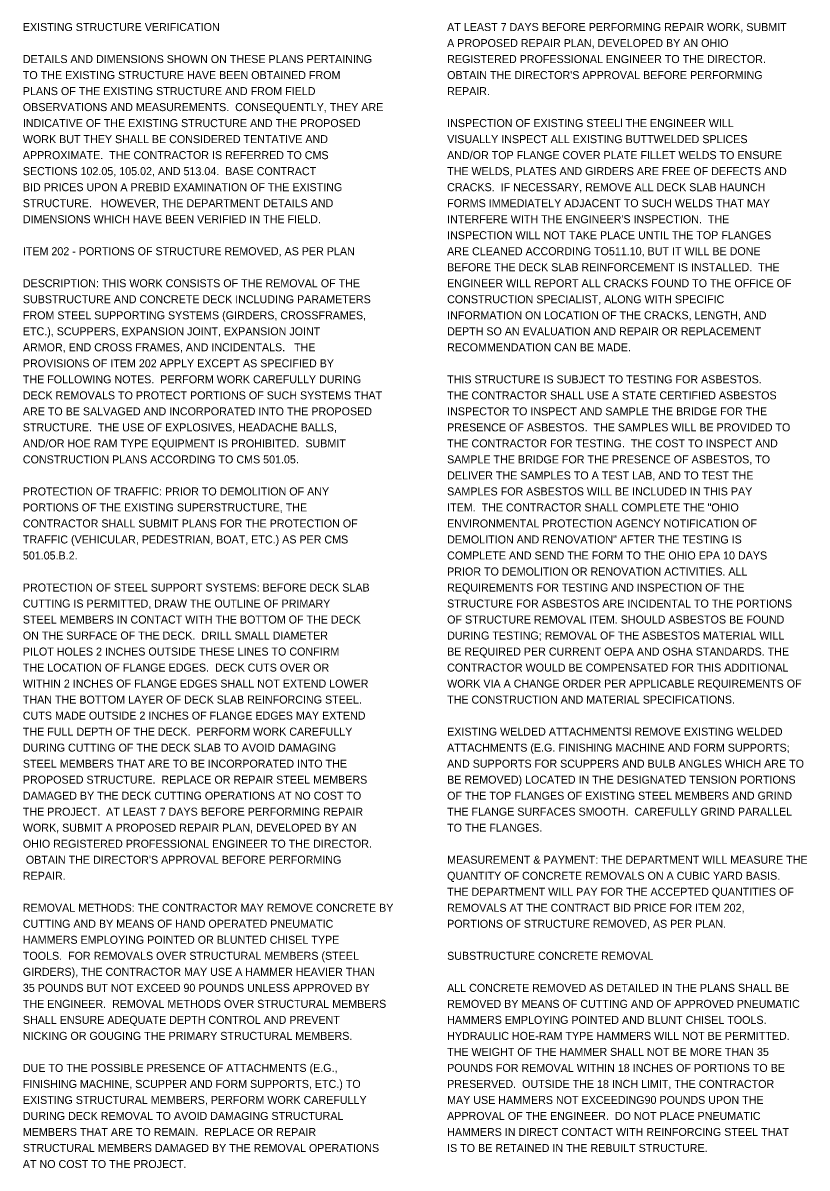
# Model space of a CAD drawing. Extents: x -51.6 to 45.5, y -38.3 to 35.3.
# Drawn here: x -44.16 to -30.45, y 15.28 to 35.3 of the extents above; entities that cross this region are included whole.
import ezdxf

# ---------------------------------------------------------------- set-up
doc = ezdxf.new("R2010")
doc.units = 0
doc.layers.add('BD_P_Text', color=7, linetype='Continuous')

msp = doc.modelspace()

# ---------------------------------------------------------------- texts
at = {"layer": 'BD_P_Text'}
for s, p in [('EXISTING STRUCTURE VERIFICATION', (-44.163, 35.157)), ('AT LEAST 7 DAYS BEFORE PERFORMING REPAIR WORK, SUBMIT ', (-36.743, 35.157)), ('A PROPOSED REPAIR PLAN, DEVELOPED BY AN OHIO ', (-36.743, 34.877)), ('DETAILS AND DIMENSIONS SHOWN ON THESE PLANS PERTAINING ', (-44.163, 34.597)), ('REGISTERED PROFESSIONAL ENGINEER TO THE DIRECTOR.  ', (-36.743, 34.597)), ('TO THE EXISTING STRUCTURE HAVE BEEN OBTAINED FROM ', (-44.163, 34.317)), ("OBTAIN THE DIRECTOR'S APPROVAL BEFORE PERFORMING ", (-36.743, 34.317)), ('PLANS OF THE EXISTING STRUCTURE AND FROM FIELD ', (-44.163, 34.037)), ('REPAIR.', (-36.743, 34.037)), ('OBSERVATIONS AND MEASUREMENTS.  CONSEQUENTLY, THEY ARE ', (-44.163, 33.757)), ('INDICATIVE OF THE EXISTING STRUCTURE AND THE PROPOSED ', (-44.163, 33.477)), ('INSPECTION OF EXISTING STEELl THE ENGINEER WILL ', (-36.743, 33.477)), ('WORK BUT THEY SHALL BE CONSIDERED TENTATIVE AND ', (-44.163, 33.197)), ('VISUALLY INSPECT ALL EXISTING BUTTWELDED SPLICES ', (-36.743, 33.197)), ('APPROXIMATE.  THE CONTRACTOR IS REFERRED TO CMS ', (-44.163, 32.917)), ('AND/OR TOP FLANGE COVER PLATE FILLET WELDS TO ENSURE ', (-36.743, 32.917)), ('SECTIONS 102.05, 105.02, AND 513.04.  BASE CONTRACT ', (-44.163, 32.637)), ('THE WELDS, PLATES AND GIRDERS ARE FREE OF DEFECTS AND ', (-36.743, 32.637)), ('BID PRICES UPON A PREBID EXAMINATION OF THE EXISTING ', (-44.163, 32.357)), ('CRACKS.  IF NECESSARY, REMOVE ALL DECK SLAB HAUNCH ', (-36.743, 32.357)), ('STRUCTURE.   HOWEVER, THE DEPARTMENT DETAILS AND ', (-44.163, 32.077)), ('FORMS IMMEDIATELY ADJACENT TO SUCH WELDS THAT MAY ', (-36.743, 32.077)), ('DIMENSIONS WHICH HAVE BEEN VERIFIED IN THE FIELD.', (-44.163, 31.797)), ("INTERFERE WITH THE ENGINEER'S INSPECTION.  THE ", (-36.743, 31.797)), ('INSPECTION WILL NOT TAKE PLACE UNTIL THE TOP FLANGES ', (-36.743, 31.517)), ('ITEM 202 - PORTIONS OF STRUCTURE REMOVED, AS PER PLAN', (-44.163, 31.237)), ('ARE CLEANED ACCORDING TO511.10, BUT IT WILL BE DONE ', (-36.743, 31.237)), ('BEFORE THE DECK SLAB REINFORCEMENT IS INSTALLED.  THE ', (-36.743, 30.957)), ('DESCRIPTION: THIS WORK CONSISTS OF THE REMOVAL OF THE ', (-44.163, 30.677)), ('ENGINEER WILL REPORT ALL CRACKS FOUND TO THE OFFICE OF ', (-36.743, 30.677)), ('SUBSTRUCTURE AND CONCRETE DECK INCLUDING PARAMETERS ', (-44.163, 30.397)), ('CONSTRUCTION SPECIALIST, ALONG WITH SPECIFIC ', (-36.743, 30.397)), ('FROM STEEL SUPPORTING SYSTEMS (GIRDERS, CROSSFRAMES, ', (-44.163, 30.117)), ('INFORMATION ON LOCATION OF THE CRACKS, LENGTH, AND ', (-36.743, 30.117)), ('ETC.), SCUPPERS, EXPANSION JOINT, EXPANSION JOINT ', (-44.163, 29.837)), ('DEPTH SO AN EVALUATION AND REPAIR OR REPLACEMENT ', (-36.743, 29.837)), ('ARMOR, END CROSS FRAMES, AND INCIDENTALS.   THE ', (-44.163, 29.557)), ('RECOMMENDATION CAN BE MADE. ', (-36.743, 29.557)), ('PROVISIONS OF ITEM 202 APPLY EXCEPT AS SPECIFIED BY ', (-44.163, 29.277)), ('THE FOLLOWING NOTES.  PERFORM WORK CAREFULLY DURING ', (-44.163, 28.997)), ('THIS STRUCTURE IS SUBJECT TO TESTING FOR ASBESTOS.  ', (-36.743, 28.997)), ('DECK REMOVALS TO PROTECT PORTIONS OF SUCH SYSTEMS THAT ', (-44.163, 28.717)), ('THE CONTRACTOR SHALL USE A STATE CERTIFIED ASBESTOS ', (-36.743, 28.717)), ('ARE TO BE SALVAGED AND INCORPORATED INTO THE PROPOSED ', (-44.163, 28.437)), ('INSPECTOR TO INSPECT AND SAMPLE THE BRIDGE FOR THE ', (-36.743, 28.437)), ('STRUCTURE.  THE USE OF EXPLOSIVES, HEADACHE BALLS, ', (-44.163, 28.157)), ('PRESENCE OF ASBESTOS.  THE SAMPLES WILL BE PROVIDED TO ', (-36.743, 28.157)), ('AND/OR HOE RAM TYPE EQUIPMENT IS PROHIBITED.  SUBMIT ', (-44.163, 27.877)), ('THE CONTRACTOR FOR TESTING.  THE COST TO INSPECT AND ', (-36.743, 27.877)), ('CONSTRUCTION PLANS ACCORDING TO CMS 501.05.', (-44.163, 27.597)), ('SAMPLE THE BRIDGE FOR THE PRESENCE OF ASBESTOS, TO ', (-36.743, 27.597)), ('DELIVER THE SAMPLES TO A TEST LAB, AND TO TEST THE ', (-36.743, 27.317)), ('PROTECTION OF TRAFFIC: PRIOR TO DEMOLITION OF ANY ', (-44.163, 27.037)), ('SAMPLES FOR ASBESTOS WILL BE INCLUDED IN THIS PAY ', (-36.743, 27.037)), ('PORTIONS OF THE EXISTING SUPERSTRUCTURE, THE ', (-44.163, 26.757)), ('ITEM.  THE CONTRACTOR SHALL COMPLETE THE "OHIO ', (-36.743, 26.757)), ('CONTRACTOR SHALL SUBMIT PLANS FOR THE PROTECTION OF ', (-44.163, 26.477)), ('ENVIRONMENTAL PROTECTION AGENCY NOTIFICATION OF ', (-36.743, 26.477)), ('TRAFFIC (VEHICULAR, PEDESTRIAN, BOAT, ETC.) AS PER CMS ', (-44.163, 26.197)), ('DEMOLITION AND RENOVATION" AFTER THE TESTING IS ', (-36.743, 26.197)), ('501.05.B.2.', (-44.163, 25.917)), ('COMPLETE AND SEND THE FORM TO THE OHIO EPA 10 DAYS ', (-36.743, 25.917)), ('PRIOR TO DEMOLITION OR RENOVATION ACTIVITIES. ALL ', (-36.743, 25.637)), ('PROTECTION OF STEEL SUPPORT SYSTEMS: BEFORE DECK SLAB ', (-44.163, 25.357)), ('REQUIREMENTS FOR TESTING AND INSPECTION OF THE ', (-36.743, 25.357)), ('CUTTING IS PERMITTED, DRAW THE OUTLINE OF PRIMARY ', (-44.163, 25.077)), ('STRUCTURE FOR ASBESTOS ARE INCIDENTAL TO THE PORTIONS ', (-36.743, 25.077)), ('STEEL MEMBERS IN CONTACT WITH THE BOTTOM OF THE DECK ', (-44.163, 24.797)), ('OF STRUCTURE REMOVAL ITEM. SHOULD ASBESTOS BE FOUND ', (-36.743, 24.797)), ('ON THE SURFACE OF THE DECK.  DRILL SMALL DIAMETER ', (-44.163, 24.517)), ('DURING TESTING; REMOVAL OF THE ASBESTOS MATERIAL WILL ', (-36.743, 24.517)), ('PILOT HOLES 2 INCHES OUTSIDE THESE LINES TO CONFIRM ', (-44.163, 24.237)), ('BE REQUIRED PER CURRENT OEPA AND OSHA STANDARDS. THE ', (-36.743, 24.237)), ('THE LOCATION OF FLANGE EDGES.  DECK CUTS OVER OR ', (-44.163, 23.957)), ('CONTRACTOR WOULD BE COMPENSATED FOR THIS ADDITIONAL ', (-36.743, 23.957)), ('WITHIN 2 INCHES OF FLANGE EDGES SHALL NOT EXTEND LOWER ', (-44.163, 23.677)), ('WORK VIA A CHANGE ORDER PER APPLICABLE REQUIREMENTS OF ', (-36.743, 23.677)), ('THAN THE BOTTOM LAYER OF DECK SLAB REINFORCING STEEL.  ', (-44.163, 23.397)), ('THE CONSTRUCTION AND MATERIAL SPECIFICATIONS.', (-36.743, 23.397)), ('CUTS MADE OUTSIDE 2 INCHES OF FLANGE EDGES MAY EXTEND ', (-44.163, 23.117)), ('THE FULL DEPTH OF THE DECK.  PERFORM WORK CAREFULLY ', (-44.163, 22.837)), ('EXISTING WELDED ATTACHMENTSl REMOVE EXISTING WELDED ', (-36.743, 22.837)), ('DURING CUTTING OF THE DECK SLAB TO AVOID DAMAGING ', (-44.163, 22.557)), ('ATTACHMENTS (E.G. FINISHING MACHINE AND FORM SUPPORTS; ', (-36.743, 22.557)), ('STEEL MEMBERS THAT ARE TO BE INCORPORATED INTO THE ', (-44.163, 22.277)), ('AND SUPPORTS FOR SCUPPERS AND BULB ANGLES WHICH ARE TO ', (-36.743, 22.277)), ('PROPOSED STRUCTURE.  REPLACE OR REPAIR STEEL MEMBERS ', (-44.163, 21.997)), ('BE REMOVED) LOCATED IN THE DESIGNATED TENSION PORTIONS ', (-36.743, 21.997)), ('DAMAGED BY THE DECK CUTTING OPERATIONS AT NO COST TO ', (-44.163, 21.717)), ('OF THE TOP FLANGES OF EXISTING STEEL MEMBERS AND GRIND ', (-36.743, 21.717)), ('THE PROJECT.  AT LEAST 7 DAYS BEFORE PERFORMING REPAIR ', (-44.163, 21.437)), ('THE FLANGE SURFACES SMOOTH.  CAREFULLY GRIND PARALLEL ', (-36.743, 21.437)), ('WORK, SUBMIT A PROPOSED REPAIR PLAN, DEVELOPED BY AN ', (-44.163, 21.157)), ('TO THE FLANGES.  ', (-36.743, 21.157)), ('OHIO REGISTERED PROFESSIONAL ENGINEER TO THE DIRECTOR. ', (-44.163, 20.877)), (" OBTAIN THE DIRECTOR'S APPROVAL BEFORE PERFORMING ", (-44.163, 20.597)), ('MEASUREMENT & PAYMENT: THE DEPARTMENT WILL MEASURE THE ', (-36.743, 20.597)), ('REPAIR.', (-44.163, 20.317)), ('QUANTITY OF CONCRETE REMOVALS ON A CUBIC YARD BASIS.  ', (-36.743, 20.317)), ('THE DEPARTMENT WILL PAY FOR THE ACCEPTED QUANTITIES OF ', (-36.743, 20.037)), ('REMOVAL METHODS: THE CONTRACTOR MAY REMOVE CONCRETE BY ', (-44.163, 19.757)), ('REMOVALS AT THE CONTRACT BID PRICE FOR ITEM 202, ', (-36.743, 19.757)), ('CUTTING AND BY MEANS OF HAND OPERATED PNEUMATIC ', (-44.163, 19.477)), ('PORTIONS OF STRUCTURE REMOVED, AS PER PLAN.', (-36.743, 19.477)), ('HAMMERS EMPLOYING POINTED OR BLUNTED CHISEL TYPE ', (-44.163, 19.197)), ('TOOLS.  FOR REMOVALS OVER STRUCTURAL MEMBERS (STEEL ', (-44.163, 18.917)), ('SUBSTRUCTURE CONCRETE REMOVAL', (-36.743, 18.917)), ('GIRDERS), THE CONTRACTOR MAY USE A HAMMER HEAVIER THAN ', (-44.163, 18.637)), ('35 POUNDS BUT NOT EXCEED 90 POUNDS UNLESS APPROVED BY ', (-44.163, 18.357)), ('ALL CONCRETE REMOVED AS DETAILED IN THE PLANS SHALL BE ', (-36.743, 18.357)), ('THE ENGINEER.  REMOVAL METHODS OVER STRUCTURAL MEMBERS ', (-44.163, 18.077)), ('REMOVED BY MEANS OF CUTTING AND OF APPROVED PNEUMATIC ', (-36.743, 18.077)), ('SHALL ENSURE ADEQUATE DEPTH CONTROL AND PREVENT ', (-44.163, 17.797)), ('HAMMERS EMPLOYING POINTED AND BLUNT CHISEL TOOLS.  ', (-36.743, 17.797)), ('NICKING OR GOUGING THE PRIMARY STRUCTURAL MEMBERS.', (-44.163, 17.517)), ('HYDRAULIC HOE-RAM TYPE HAMMERS WILL NOT BE PERMITTED.  ', (-36.743, 17.517)), ('THE WEIGHT OF THE HAMMER SHALL NOT BE MORE THAN 35 ', (-36.743, 17.237)), ('DUE TO THE POSSIBLE PRESENCE OF ATTACHMENTS (E.G., ', (-44.163, 16.957)), ('POUNDS FOR REMOVAL WITHIN 18 INCHES OF PORTIONS TO BE ', (-36.743, 16.957)), ('FINISHING MACHINE, SCUPPER AND FORM SUPPORTS, ETC.) TO ', (-44.163, 16.677)), ('PRESERVED.  OUTSIDE THE 18 INCH LIMIT, THE CONTRACTOR ', (-36.743, 16.677)), ('EXISTING STRUCTURAL MEMBERS, PERFORM WORK CAREFULLY ', (-44.163, 16.397)), ('MAY USE HAMMERS NOT EXCEEDING90 POUNDS UPON THE ', (-36.743, 16.397)), ('DURING DECK REMOVAL TO AVOID DAMAGING STRUCTURAL ', (-44.163, 16.117)), ('APPROVAL OF THE ENGINEER.  DO NOT PLACE PNEUMATIC ', (-36.743, 16.117)), ('MEMBERS THAT ARE TO REMAIN.  REPLACE OR REPAIR ', (-44.163, 15.837)), ('HAMMERS IN DIRECT CONTACT WITH REINFORCING STEEL THAT ', (-36.743, 15.837)), ('STRUCTURAL MEMBERS DAMAGED BY THE REMOVAL OPERATIONS ', (-44.163, 15.557)), ('IS TO BE RETAINED IN THE REBUILT STRUCTURE. ', (-36.743, 15.557)), ('AT NO COST TO THE PROJECT.', (-44.163, 15.277))]:
    msp.add_text(s, height=0.14, dxfattribs=at).set_placement(p)

doc.saveas('drawing.dxf')
